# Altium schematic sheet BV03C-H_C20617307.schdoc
size 127 x 101 mm
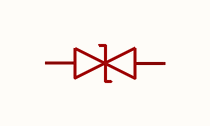
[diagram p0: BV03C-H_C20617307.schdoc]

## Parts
D?  bv03c-h_c20617307  [SOD-323_L1.7-W1.3-LS2.5-BI-1]  (value not drawn)

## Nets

Not connected (* = marked no-connect by the designer): D? 1 2

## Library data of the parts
D? = bv03c-h_c20617307: Manufacturer: TECH PUBLIC(台舟); AddInBom: yes; ModelId: 5bffd34da2d34048ab2043cf4ece0d8f; ModelTransform: 102.362,51.181,0,0,0,0,0,0,0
